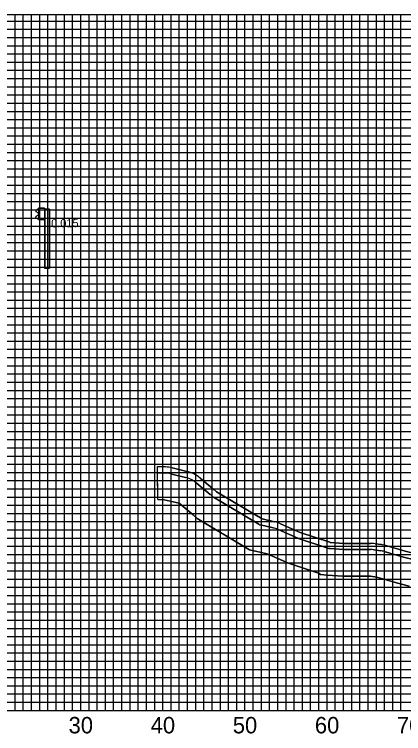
# Model space of a CAD drawing. Extents: x -109 to 149, y 1173 to 1269.
# Drawn here: x 21.9 to 69.3, y 1177.2 to 1264.8 of the extents above; entities that cross this region are included whole.
import ezdxf

# ---------------------------------------------------------------- set-up
doc = ezdxf.new("R2010")
doc.units = 0
for name, color, linetype in [('DES - SHEET - Light Grid', 7, 'Continuous'), ('DES - SHEET - Linework', 7, 'Continuous'), ('DES - TRAN - Proposed Layout Patterning', 7, 'Continuous'), ('DES - XS - Proposed - Finished Grade Slopes Text', 7, 'Continuous'), ('DES - XS - Proposed - Guardrail', 7, 'Continuous'), ('DES - XS - Proposed - Text', 7, 'Continuous')]:
    doc.layers.add(name, color=color, linetype=linetype)

msp = doc.modelspace()

# ---------------------------------------------------------------- linework, layer by layer
at = {"layer": 'DES - SHEET - Light Grid'}
for p, q in [((22, 1180), (22, 1264.814)), ((23, 1180), (23, 1264.814)), ((24, 1180), (24, 1264.814)), ((25, 1180), (25, 1264.814)), ((26, 1180), (26, 1264.814)), ((27, 1180), (27, 1264.814)), ((28, 1180), (28, 1264.814)), ((29, 1180), (29, 1264.814)), ((31, 1180), (31, 1264.814)), ((32, 1180), (32, 1264.814)), ((33, 1180), (33, 1264.814)), ((34, 1180), (34, 1264.814)), ((35, 1180), (35, 1264.814)), ((36, 1180), (36, 1264.814)), ((37, 1180), (37, 1264.814)), ((38, 1180), (38, 1264.814)), ((39, 1180), (39, 1264.814)), ((41, 1180), (41, 1264.814)), ((42, 1180), (42, 1264.814)), ((43, 1180), (43, 1264.814)), ((44, 1180), (44, 1264.814)), ((45, 1180), (45, 1264.814)), ((46, 1180), (46, 1264.814)), ((47, 1180), (47, 1264.814)), ((48, 1180), (48, 1264.814)), ((49, 1180), (49, 1264.814)), ((51, 1180), (51, 1264.814)), ((52, 1180), (52, 1264.814)), ((53, 1180), (53, 1264.814)), ((54, 1180), (54, 1264.814)), ((55, 1180), (55, 1264.814)), ((56, 1180), (56, 1264.814)), ((57, 1180), (57, 1264.814)), ((58, 1180), (58, 1264.814)), ((59, 1180), (59, 1264.814)), ((61, 1180), (61, 1264.814)), ((62, 1180), (62, 1264.814)), ((63, 1180), (63, 1264.814)), ((64, 1180), (64, 1264.814)), ((65, 1180), (65, 1264.814)), ((66, 1180), (66, 1264.814)), ((67, 1180), (67, 1264.814)), ((68, 1180), (68, 1264.814)), ((69, 1180), (69, 1264.814)), ((-100, 1264), (140, 1264)), ((-100, 1263), (140, 1263)), ((-100, 1262), (140, 1262)), ((-100, 1261), (140, 1261)), ((-100, 1259), (140, 1259)), ((-100, 1258), (140, 1258)), ((-100, 1257), (140, 1257)), ((-100, 1256), (140, 1256)), ((-100, 1255), (140, 1255)), ((-100, 1254), (140, 1254)), ((-100, 1253), (140, 1253)), ((-100, 1252), (140, 1252)), ((-100, 1251), (140, 1251)), ((-100, 1249), (140, 1249)), ((-100, 1248), (140, 1248)), ((-100, 1247), (140, 1247)), ((-100, 1246), (140, 1246)), ((-100, 1245), (140, 1245)), ((-100, 1244), (140, 1244)), ((-100, 1243), (140, 1243)), ((-100, 1242), (140, 1242)), ((-100, 1241), (140, 1241)), ((-100, 1239), (140, 1239)), ((-100, 1238), (140, 1238)), ((-100, 1237), (140, 1237)), ((-100, 1236), (140, 1236)), ((-100, 1235), (140, 1235)), ((-100, 1234), (140, 1234)), ((-100, 1233), (140, 1233)), ((-100, 1232), (140, 1232)), ((-100, 1231), (140, 1231)), ((-100, 1229), (140, 1229)), ((-100, 1228), (140, 1228)), ((-100, 1227), (140, 1227)), ((-100, 1226), (140, 1226)), ((-100, 1225), (140, 1225)), ((-100, 1224), (140, 1224)), ((-100, 1223), (140, 1223)), ((-100, 1222), (140, 1222)), ((-100, 1221), (140, 1221)), ((-100, 1219), (140, 1219)), ((-100, 1218), (140, 1218)), ((-100, 1217), (140, 1217)), ((-100, 1216), (140, 1216)), ((-100, 1215), (140, 1215)), ((-100, 1214), (140, 1214)), ((-100, 1213), (140, 1213)), ((-100, 1212), (140, 1212)), ((-100, 1211), (140, 1211)), ((-100, 1209), (140, 1209)), ((-100, 1208), (140, 1208)), ((-100, 1207), (140, 1207)), ((-100, 1206), (140, 1206)), ((-100, 1205), (140, 1205)), ((-100, 1204), (140, 1204)), ((-100, 1203), (140, 1203)), ((-100, 1202), (140, 1202)), ((-100, 1201), (140, 1201)), ((-100, 1199), (140, 1199)), ((-100, 1198), (140, 1198)), ((-100, 1197), (140, 1197)), ((-100, 1196), (140, 1196)), ((-100, 1195), (140, 1195)), ((-100, 1194), (140, 1194)), ((-100, 1193), (140, 1193)), ((-100, 1192), (140, 1192)), ((-100, 1191), (140, 1191)), ((-100, 1189), (140, 1189)), ((-100, 1188), (140, 1188)), ((-100, 1187), (140, 1187)), ((-100, 1186), (140, 1186)), ((-100, 1185), (140, 1185)), ((-100, 1184), (140, 1184)), ((-100, 1183), (140, 1183)), ((-100, 1182), (140, 1182)), ((-100, 1181), (140, 1181))]:
    msp.add_line(p, q, dxfattribs=at)
at = {"layer": 'DES - SHEET - Linework'}
for p, q in [((-100, 1264.814), (140, 1264.814)), ((30, 1180), (30, 1264.814)), ((40, 1180), (40, 1264.814)), ((50, 1180), (50, 1264.814)), ((60, 1180), (60, 1264.814)), ((-100, 1260), (140, 1260)), ((-100, 1250), (140, 1250)), ((-100, 1240), (140, 1240)), ((-100, 1230), (140, 1230)), ((-100, 1220), (140, 1220)), ((-100, 1210), (140, 1210)), ((-100, 1200), (140, 1200)), ((-100, 1190), (140, 1190)), ((-100, 1180), (140, 1180))]:
    msp.add_line(p, q, dxfattribs=at)
at = {"layer": 'DES - TRAN - Proposed Layout Patterning'}
for p, q in [((39.37, 1205.701), (39.361, 1209.704)), ((40.316, 1209.67), (39.361, 1209.704)), ((42.919, 1209.122), (41.118, 1209.56)), ((41.118, 1209.56), (42.919, 1209.122)), ((41.118, 1209.56), (42.919, 1209.122)), ((41.118, 1209.56), (42.919, 1209.122)), ((40.289, 1208.92), (39.363, 1208.953)), ((42.742, 1208.394), (40.941, 1208.831)), ((40.941, 1208.831), (42.742, 1208.394)), ((40.941, 1208.831), (42.742, 1208.394)), ((42.742, 1208.394), (40.941, 1208.831)), ((42.742, 1208.394), (40.941, 1208.831)), ((45.755, 1206.316), (44.056, 1207.732)), ((44.056, 1207.732), (45.755, 1206.316)), ((44.056, 1207.732), (45.755, 1206.316)), ((45.755, 1206.316), (44.056, 1207.732)), ((45.755, 1206.316), (44.056, 1207.732)), ((46.235, 1206.892), (44.537, 1208.308)), ((44.537, 1208.308), (46.235, 1206.892)), ((44.537, 1208.308), (46.235, 1206.892)), ((44.537, 1208.308), (46.235, 1206.892)), ((46.047, 1206.067), (45.781, 1206.294)), ((45.781, 1206.294), (46.047, 1206.067)), ((45.781, 1206.294), (46.047, 1206.067)), ((46.047, 1206.067), (45.781, 1206.294)), ((46.047, 1206.067), (45.781, 1206.294)), ((51.689, 1202.682), (46.148, 1205.995)), ((46.148, 1205.995), (51.689, 1202.682)), ((46.148, 1205.995), (51.689, 1202.682)), ((51.689, 1202.682), (46.148, 1205.995)), ((51.689, 1202.682), (46.148, 1205.995)), ((53.415, 1202.254), (51.909, 1202.594)), ((51.909, 1202.594), (53.415, 1202.254)), ((51.909, 1202.594), (53.415, 1202.254)), ((53.415, 1202.254), (51.909, 1202.594)), ((53.415, 1202.254), (51.909, 1202.594)), ((56.431, 1200.98), (54.023, 1202.053)), ((54.023, 1202.053), (56.431, 1200.98)), ((54.023, 1202.053), (56.431, 1200.98)), ((56.431, 1200.98), (54.023, 1202.053)), ((56.431, 1200.98), (54.023, 1202.053)), ((60.084, 1199.781), (56.503, 1200.952)), ((56.503, 1200.952), (60.084, 1199.781)), ((56.503, 1200.952), (60.084, 1199.781)), ((60.084, 1199.781), (56.503, 1200.952)), ((60.084, 1199.781), (56.503, 1200.952)), ((66.618, 1200.198), (65.84, 1200.308)), ((65.84, 1200.308), (66.618, 1200.198)), ((65.84, 1200.308), (66.618, 1200.198)), ((65.84, 1200.308), (66.618, 1200.198)), ((60.356, 1199.721), (60.3, 1199.727)), ((60.3, 1199.727), (60.356, 1199.721)), ((60.3, 1199.727), (60.356, 1199.721)), ((60.356, 1199.721), (60.3, 1199.727)), ((60.356, 1199.721), (60.3, 1199.727)), ((61.985, 1199.597), (60.379, 1199.719)), ((60.379, 1199.719), (61.985, 1199.597)), ((60.379, 1199.719), (61.985, 1199.597)), ((61.985, 1199.597), (60.379, 1199.719)), ((61.985, 1199.597), (60.379, 1199.719)), ((65.279, 1199.597), (62.043, 1199.595)), ((62.043, 1199.595), (65.279, 1199.597)), ((62.043, 1199.595), (65.279, 1199.597)), ((65.279, 1199.597), (62.043, 1199.595)), ((65.279, 1199.597), (62.043, 1199.595)), ((66.513, 1199.456), (65.735, 1199.565)), ((65.735, 1199.565), (66.513, 1199.456)), ((65.735, 1199.565), (66.513, 1199.456)), ((66.513, 1199.456), (65.735, 1199.565)), ((66.513, 1199.456), (65.735, 1199.565)), ((69.299, 1198.68), (66.967, 1199.358)), ((66.967, 1199.358), (69.299, 1198.68)), ((66.967, 1199.358), (69.299, 1198.68)), ((69.299, 1198.68), (66.967, 1199.358)), ((69.299, 1198.68), (66.967, 1199.358)), ((69.322, 1198.673), (70.653, 1198.333)), ((70.653, 1198.333), (69.322, 1198.673))]:
    msp.add_line(p, q, dxfattribs=at)
for points in [[(70.015, 1195.141), (68.454, 1195.541), (66.059, 1196.237), (65.281, 1196.347), (61.892, 1196.345), (60.071, 1196.483), (59.177, 1196.579), (59.074, 1196.692), (55.297, 1197.927), (52.7, 1199.084), (50.57, 1199.565), (44.194, 1203.377), (43.674, 1203.82), (41.975, 1205.235), (40.174, 1205.672), (39.37, 1205.701), (39.361, 1209.704), (40.316, 1209.67)], [(40.289, 1208.92), (39.363, 1208.953), (39.361, 1209.704), (40.316, 1209.67)], [(40.289, 1208.92), (39.363, 1208.953), (39.361, 1209.704), (40.316, 1209.67)], [(70.015, 1195.141), (68.454, 1195.541), (66.059, 1196.237), (65.281, 1196.347), (61.892, 1196.345), (60.071, 1196.483), (59.177, 1196.579), (59.074, 1196.692), (55.297, 1197.927), (52.7, 1199.084), (50.57, 1199.565), (44.194, 1203.377), (43.674, 1203.82), (41.975, 1205.235), (40.174, 1205.672), (39.37, 1205.701), (39.363, 1208.953), (40.289, 1208.92)], [(70.015, 1195.141), (68.454, 1195.541), (66.059, 1196.237), (65.281, 1196.347), (61.892, 1196.345), (60.071, 1196.483), (59.177, 1196.579), (59.074, 1196.692), (55.297, 1197.927), (52.7, 1199.084), (50.57, 1199.565), (44.194, 1203.377), (43.674, 1203.82), (41.975, 1205.235), (40.174, 1205.672), (39.37, 1205.701), (39.363, 1208.953), (40.289, 1208.92)], [(53.58, 1202.986), (52.074, 1203.326), (46.533, 1206.638), (46.268, 1206.864)], [(46.268, 1206.864), (46.533, 1206.638), (52.074, 1203.326), (53.58, 1202.986)], [(46.268, 1206.864), (46.533, 1206.638), (52.074, 1203.326), (53.58, 1202.986)], [(46.268, 1206.864), (46.533, 1206.638), (52.074, 1203.326), (53.58, 1202.986)], [(39.37, 1205.701), (40.174, 1205.672), (41.975, 1205.235), (43.674, 1203.82), (44.194, 1203.377), (50.57, 1199.565), (52.7, 1199.084), (55.297, 1197.927), (59.074, 1196.692), (59.177, 1196.579), (60.071, 1196.483), (61.892, 1196.345), (65.281, 1196.347), (66.059, 1196.237), (68.454, 1195.541), (70.015, 1195.141)], [(60.317, 1200.494), (56.736, 1201.665), (54.328, 1202.738)], [(54.328, 1202.738), (56.736, 1201.665), (60.317, 1200.494)], [(54.328, 1202.738), (56.736, 1201.665), (60.317, 1200.494)], [(54.328, 1202.738), (56.736, 1201.665), (60.317, 1200.494)], [(65.279, 1200.347), (62.042, 1200.345), (60.436, 1200.467), (60.38, 1200.473)], [(60.38, 1200.473), (60.436, 1200.467), (62.042, 1200.345), (65.279, 1200.347)], [(60.38, 1200.473), (60.436, 1200.467), (62.042, 1200.345), (65.279, 1200.347)], [(60.38, 1200.473), (60.436, 1200.467), (62.042, 1200.345), (65.279, 1200.347)], [(76.133, 1198.582), (75.289, 1198.492), (75.198, 1198.497), (72.417, 1198.798), (70.839, 1199.059), (69.508, 1199.4), (67.176, 1200.078)], [(67.176, 1200.078), (69.508, 1199.4), (70.839, 1199.059), (72.417, 1198.798), (75.198, 1198.497), (75.289, 1198.492), (76.133, 1198.582)], [(67.176, 1200.078), (69.508, 1199.4), (70.839, 1199.059), (72.417, 1198.798), (75.198, 1198.497), (75.289, 1198.492), (76.133, 1198.582)], [(67.176, 1200.078), (69.508, 1199.4), (70.839, 1199.059), (72.417, 1198.798), (75.198, 1198.497), (75.289, 1198.492), (76.133, 1198.582)]]:
    msp.add_lwpolyline(points, dxfattribs=at)
for centre, radius, start, end in [((40.174, 1205.672), 4, 76.35618, 87.97682), ((40.174, 1205.672), 4, 76.35618, 87.97682), ((40.174, 1205.672), 4, 76.35618, 87.97682), ((40.174, 1205.672), 4, 76.35618, 87.97682), ((40.174, 1205.672), 3.25, 76.35618, 87.97682), ((40.174, 1205.672), 3.25, 76.35618, 87.97682), ((40.174, 1205.672), 3.25, 76.35618, 87.97682), ((40.174, 1205.672), 3.25, 76.35618, 87.97682), ((40.174, 1205.672), 3.25, 76.35618, 87.97682), ((41.975, 1205.235), 4, 50.18535, 76.35618), ((41.975, 1205.235), 4, 50.18535, 76.35618), ((41.975, 1205.235), 4, 50.18535, 76.35618), ((41.975, 1205.235), 4, 50.18535, 76.35618), ((41.975, 1205.235), 3.25, 50.18535, 76.35618), ((41.975, 1205.235), 3.25, 50.18535, 76.35618), ((41.975, 1205.235), 3.25, 50.18535, 76.35618), ((41.975, 1205.235), 3.25, 50.18535, 76.35618), ((41.975, 1205.235), 3.25, 50.18535, 76.35618), ((43.674, 1203.82), 4, 49.5679, 50.18535), ((43.674, 1203.82), 4, 49.5679, 50.18535), ((43.674, 1203.82), 4, 49.5679, 50.18535), ((43.674, 1203.82), 4, 49.5679, 50.18535), ((43.674, 1203.82), 3.25, 49.5679, 50.18535), ((43.674, 1203.82), 3.25, 49.5679, 50.18535), ((43.674, 1203.82), 3.25, 49.5679, 50.18535), ((43.674, 1203.82), 3.25, 49.5679, 50.18535), ((43.674, 1203.82), 3.25, 49.5679, 50.18535), ((46.533, 1206.638), 0.75, 229.5679, 239.1279), ((46.533, 1206.638), 0.75, 229.5679, 239.1279), ((46.533, 1206.638), 0.75, 229.5679, 239.1279), ((46.533, 1206.638), 0.75, 229.5679, 239.1279), ((46.533, 1206.638), 0.75, 229.5679, 239.1279), ((52.074, 1203.326), 0.75, 239.1279, 257.28921), ((52.074, 1203.326), 0.75, 239.1279, 257.28921), ((52.074, 1203.326), 0.75, 239.1279, 257.28921), ((52.074, 1203.326), 0.75, 239.1279, 257.28921), ((52.074, 1203.326), 0.75, 239.1279, 257.28921), ((52.7, 1199.084), 4, 65.98795, 77.28921), ((52.7, 1199.084), 4, 65.98795, 77.28921), ((52.7, 1199.084), 4, 65.98795, 77.28921), ((52.7, 1199.084), 4, 65.98795, 77.28921), ((52.7, 1199.084), 3.25, 65.98795, 77.28921), ((52.7, 1199.084), 3.25, 65.98795, 77.28921), ((52.7, 1199.084), 3.25, 65.98795, 77.28921), ((52.7, 1199.084), 3.25, 65.98795, 77.28921), ((52.7, 1199.084), 3.25, 65.98795, 77.28921), ((56.736, 1201.665), 0.75, 245.98795, 251.89357), ((56.736, 1201.665), 0.75, 245.98795, 251.89357), ((56.736, 1201.665), 0.75, 245.98795, 251.89357), ((56.736, 1201.665), 0.75, 245.98795, 251.89357), ((56.736, 1201.665), 0.75, 245.98795, 251.89357), ((59.074, 1196.692), 4, 70.94289, 71.89357), ((59.074, 1196.692), 4, 70.94289, 71.89357), ((59.074, 1196.692), 4, 70.94289, 71.89357), ((59.074, 1196.692), 4, 70.94289, 71.89357), ((65.281, 1196.347), 4, 81.97091, 90.0402), ((65.281, 1196.347), 4, 81.97091, 90.0402), ((65.281, 1196.347), 4, 81.97091, 90.0402), ((65.281, 1196.347), 4, 81.97091, 90.0402), ((66.059, 1196.237), 4, 73.7841, 81.97091), ((66.059, 1196.237), 4, 73.7841, 81.97091), ((66.059, 1196.237), 4, 73.7841, 81.97091), ((66.059, 1196.237), 4, 73.7841, 81.97091), ((59.074, 1196.692), 3.25, 70.94289, 71.89357), ((59.074, 1196.692), 3.25, 70.94289, 71.89357), ((59.074, 1196.692), 3.25, 70.94289, 71.89357), ((59.074, 1196.692), 3.25, 70.94289, 71.89357), ((59.074, 1196.692), 3.25, 70.94289, 71.89357), ((60.38, 1200.473), 0.75, 250.94289, 263.88964), ((60.38, 1200.473), 0.75, 250.94289, 263.88964), ((60.38, 1200.473), 0.75, 250.94289, 263.88964), ((60.38, 1200.473), 0.75, 250.94289, 263.88964), ((60.38, 1200.473), 0.75, 250.94289, 263.88964), ((60.436, 1200.467), 0.75, 263.88964, 265.64865), ((60.436, 1200.467), 0.75, 263.88964, 265.64865), ((60.436, 1200.467), 0.75, 263.88964, 265.64865), ((60.436, 1200.467), 0.75, 263.88964, 265.64865), ((60.436, 1200.467), 0.75, 263.88964, 265.64865), ((62.042, 1200.345), 0.75, 265.64865, 270.0402), ((62.042, 1200.345), 0.75, 265.64865, 270.0402), ((62.042, 1200.345), 0.75, 265.64865, 270.0402), ((62.042, 1200.345), 0.75, 265.64865, 270.0402), ((62.042, 1200.345), 0.75, 265.64865, 270.0402), ((65.281, 1196.347), 3.25, 81.97091, 90.0402), ((65.281, 1196.347), 3.25, 81.97091, 90.0402), ((65.281, 1196.347), 3.25, 81.97091, 90.0402), ((65.281, 1196.347), 3.25, 81.97091, 90.0402), ((65.281, 1196.347), 3.25, 81.97091, 90.0402), ((66.059, 1196.237), 3.25, 73.7841, 81.97091), ((66.059, 1196.237), 3.25, 73.7841, 81.97091), ((66.059, 1196.237), 3.25, 73.7841, 81.97091), ((66.059, 1196.237), 3.25, 73.7841, 81.97091), ((66.059, 1196.237), 3.25, 73.7841, 81.97091), ((69.508, 1199.4), 0.75, 253.7841, 255.64195), ((69.508, 1199.4), 0.75, 253.7841, 255.64195), ((69.508, 1199.4), 0.75, 253.7841, 255.64195), ((69.508, 1199.4), 0.75, 253.7841, 255.64195), ((69.508, 1199.4), 0.75, 253.7841, 255.64195)]:
    msp.add_arc(centre, radius, start, end, dxfattribs=at)
at = {"layer": 'DES - XS - Proposed - Guardrail'}
for p, q in [((24.675, 1241.046), (24.542, 1240.954)), ((24.834, 1241.103), (24.795, 1241.096)), ((24.847, 1241.202), (24.847, 1241.202)), ((24.847, 1241.202), (25.597, 1241.202)), ((25.597, 1241.202), (24.847, 1241.202)), ((24.847, 1241.202), (24.847, 1239.802)), ((24.847, 1241.202), (24.847, 1239.802)), ((25.597, 1241.202), (25.597, 1241.202)), ((25.597, 1241.202), (25.597, 1239.802)), ((25.597, 1241.202), (25.597, 1239.802)), ((25.597, 1241.091), (25.597, 1241.091)), ((25.597, 1241.091), (25.616, 1241.091)), ((25.616, 1241.091), (25.597, 1241.091)), ((25.597, 1241.091), (25.597, 1233.891)), ((25.597, 1241.091), (25.597, 1233.891)), ((25.616, 1241.091), (25.616, 1241.091)), ((25.616, 1241.091), (26.16, 1241.091)), ((26.16, 1241.091), (25.616, 1241.091)), ((25.616, 1241.091), (25.616, 1241.091)), ((25.616, 1241.091), (25.616, 1233.891)), ((25.616, 1241.091), (25.616, 1233.891)), ((25.616, 1241.091), (25.616, 1233.891)), ((25.616, 1241.091), (25.616, 1233.891)), ((26.16, 1241.091), (26.16, 1241.091)), ((26.16, 1241.091), (26.18, 1241.091)), ((26.18, 1241.091), (26.16, 1241.091)), ((26.16, 1241.091), (26.16, 1241.091)), ((26.16, 1241.091), (26.16, 1233.891)), ((26.16, 1241.091), (26.16, 1233.891)), ((26.16, 1241.091), (26.16, 1233.891)), ((26.16, 1241.091), (26.16, 1233.891)), ((26.18, 1241.091), (26.18, 1241.091)), ((26.18, 1241.091), (26.18, 1233.891)), ((26.18, 1241.091), (26.18, 1233.891)), ((24.542, 1240.8), (24.794, 1240.624)), ((24.794, 1240.358), (24.542, 1240.181)), ((24.834, 1240.547), (24.834, 1240.434)), ((24.542, 1240.028), (24.675, 1239.935)), ((24.795, 1239.885), (24.834, 1239.878)), ((24.847, 1239.802), (24.847, 1239.802)), ((24.847, 1239.802), (25.597, 1239.802)), ((25.597, 1239.802), (24.847, 1239.802)), ((25.597, 1239.802), (25.597, 1239.802)), ((25.597, 1233.891), (25.597, 1233.891)), ((25.597, 1233.891), (25.616, 1233.891)), ((25.616, 1233.891), (25.597, 1233.891)), ((25.616, 1233.891), (25.616, 1233.891)), ((25.616, 1233.891), (26.16, 1233.891)), ((26.16, 1233.891), (25.616, 1233.891)), ((25.616, 1233.891), (25.616, 1233.891)), ((26.16, 1233.891), (26.16, 1233.891)), ((26.16, 1233.891), (26.18, 1233.891)), ((26.18, 1233.891), (26.16, 1233.891)), ((26.16, 1233.891), (26.16, 1233.891)), ((26.18, 1233.891), (26.18, 1233.891))]:
    msp.add_line(p, q, dxfattribs=at)
for centre, radius, start, end in [((24.847, 1240.801), 0.3, 100, 125), ((24.596, 1240.877), 0.0938, 125, 235), ((24.596, 1240.104), 0.0938, 125, 235), ((24.741, 1240.547), 0.0938, 0, 55), ((24.741, 1240.434), 0.0937, 305, 0), ((24.847, 1240.18), 0.3, 235, 260)]:
    msp.add_arc(centre, radius, start, end, dxfattribs=at)

# ---------------------------------------------------------------- texts
at = {"layer": 'DES - XS - Proposed - Finished Grade Slopes Text'}
msp.add_text('0.015', height=1, rotation=0.85937, dxfattribs=at).set_placement((26.39, 1238.844))
at = {"layer": 'DES - XS - Proposed - Text'}
for s, p in [('30', (28.514, 1177.2)), ('40', (38.514, 1177.2)), ('50', (48.514, 1177.2)), ('60', (58.514, 1177.2)), ('70', (68.514, 1177.2))]:
    msp.add_text(s, height=2, dxfattribs=at).set_placement(p)

doc.saveas('drawing.dxf')
